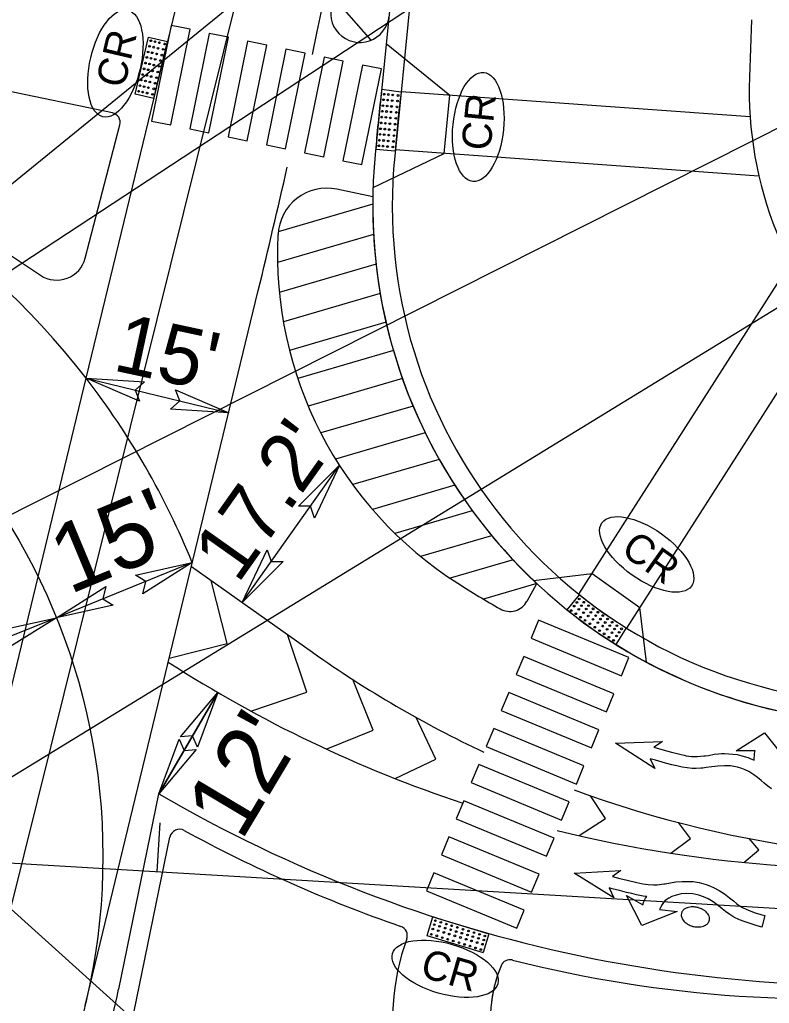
# Model space of a CAD drawing. Extents: x 2010838 to 2015151, y 441905 to 447792.
# Drawn here: x 2012023.9 to 2012100.7, y 444972.1 to 445072.8 of the extents above; entities that cross this region are included whole.
import ezdxf

# ---------------------------------------------------------------- set-up
doc = ezdxf.new("R2010")
doc.units = 0
for name, color, linetype in [('1-BUFFER', 7, 'Continuous'), ('A-Wall-Abov', 7, 'Continuous'), ('C-Alignment Geometry', 7, 'Continuous'), ('C-Building', 7, 'Continuous'), ('C-CURB STOPS', 7, 'Continuous'), ('C-Grave Plots', 7, 'Continuous'), ('C-Surface', 7, 'Continuous'), ('CLRD', 7, 'Continuous'), ('Default_10ft_LIDAR_Contou', 7, 'Continuous'), ('HATCH', 7, 'Continuous'), ('s-Existing Major', 7, 'Continuous'), ('S-Existing Minor', 7, 'Continuous'), ('S-overhead electric', 7, 'Continuous'), ('TEXT-LG', 7, 'Continuous'), ('TEXT-MED', 7, 'Continuous'), ('X4', 7, 'Continuous')]:
    doc.layers.add(name, color=color, linetype=linetype)

msp = doc.modelspace()

# ---------------------------------------------------------------- linework, layer by layer
at = {"layer": '1-BUFFER'}
msp.add_line((2012098.84, 445072.81), (2012098.63, 445066.91), dxfattribs=at)
msp.add_arc((2012137.61, 445065.53), 39, 177.9766, 273.0671, dxfattribs=at)
at = {"layer": 'A-Wall-Abov'}
msp.add_lwpolyline([(2012100.89, 444994.06), (2012100.5, 444994.33), (2012100.14, 444994.62), (2012099.83, 444994.91), (2012099.45, 444995.21), (2012099.08, 444995.49), (2012098.57, 444995.81), (2012098.2, 444996), (2012097.84, 444996.14), (2012097.42, 444996.26), (2012097.05, 444996.34), (2012096.71, 444996.39), (2012096.46, 444996.4), (2012096.09, 444996.39), (2012095.4, 444996.35), (2012094.77, 444996.29), (2012094.2, 444996.22), (2012093.85, 444996.17), (2012093.67, 444996.15), (2012093.19, 444996.12), (2012092.76, 444996.13), (2012092.26, 444996.18), (2012091.74, 444996.27), (2012091.19, 444996.39), (2012090.7, 444996.51), (2012090.05, 444996.69), (2012089.03, 444996.98), (2012088.48, 444997.13), (2012088.94, 444996.12), (2012084.93, 444998.73), (2012089.72, 444998.88), (2012088.89, 444998.32), (2012088.85, 444998.3), (2012090.13, 444997.94), (2012090.78, 444997.77), (2012091.09, 444997.69), (2012091.63, 444997.56), (2012091.94, 444997.48), (2012092.14, 444997.44), (2012092.69, 444997.37), (2012093.06, 444997.36), (2012093.33, 444997.36), (2012093.62, 444997.38), (2012093.95, 444997.41), (2012094.15, 444997.43), (2012094.45, 444997.47), (2012095.03, 444997.58), (2012095.45, 444997.63), (2012095.77, 444997.65), (2012096.07, 444997.65), (2012096.52, 444997.64), (2012096.92, 444997.61), (2012097.39, 444997.55), (2012097.86, 444997.44), (2012098.24, 444997.33), (2012098.51, 444997.24), (2012098.71, 444997.16), (2012099.1, 444996.98), (2012099.11, 444997.18), (2012099.14, 444997.47), (2012099.16, 444997.66), (2012099.21, 444997.94), (2012097.29, 444997.93), (2012100.18, 444999.79), (2012102.59, 444996.74)], dxfattribs=at)
msp.add_lwpolyline([(2012080.69, 444985.42), (2012085.48, 444985.67), (2012084.63, 444985.07), (2012085.38, 444984.88), (2012086.11, 444984.69), (2012087.12, 444984.45), (2012087.72, 444984.32), (2012088.27, 444984.24), (2012088.81, 444984.22), (2012089.2, 444984.23), (2012089.88, 444984.31), (2012090.02, 444984.32), (2012091.11, 444984.52), (2012091.74, 444984.57), (2012092.33, 444984.57), (2012092.86, 444984.54), (2012093.5, 444984.44), (2012094.19, 444984.25), (2012094.66, 444984.07), (2012094.96, 444983.94), (2012095.52, 444983.63), (2012096.07, 444983.28), (2012096.6, 444982.9), (2012096.99, 444982.59), (2012097.32, 444982.31), (2012097.52, 444982.13), (2012097.91, 444981.9), (2012098.6, 444981.57), (2012099.22, 444981.33), (2012099.79, 444981.16), (2012100.22, 444981.06), (2012099.91, 444979.87), (2012099.31, 444980.04), (2012098.69, 444980.24), (2012098.08, 444980.45), (2012097.61, 444980.63), (2012097.03, 444980.92), (2012096.61, 444981.17), (2012096.18, 444981.47), (2012095.84, 444981.76), (2012095.47, 444982.07), (2012094.91, 444982.47), (2012094.41, 444982.77), (2012093.93, 444983), (2012093.45, 444983.16), (2012092.83, 444983.29), (2012092.24, 444983.33), (2012091.64, 444983.3), (2012091.13, 444983.17), (2012090.69, 444983.02), (2012090.37, 444982.86), (2012090.02, 444982.62), (2012089.83, 444982.41), (2012089.69, 444982.21), (2012089.52, 444981.89), (2012089.44, 444981.69), (2012091.25, 444981.5), (2012087.63, 444980.06), (2012086.06, 444983.12), (2012087.71, 444982.15), (2012087.8, 444982.42), (2012087.89, 444982.63), (2012088, 444982.84), (2012088.13, 444983.02), (2012087.75, 444983.07), (2012087.09, 444983.19), (2012086.58, 444983.31), (2012086.06, 444983.44), (2012085.35, 444983.62), (2012084.6, 444983.81), (2012084.27, 444983.9), (2012084.76, 444982.9)], close=True, dxfattribs=at)
for centre, radius, start, end in [((2012092.39, 444981.11), 0.742, 166.791, 189.9046), ((2012092.27, 444981.14), 0.613, 165.5576, 166.791), ((2012092.39, 444981.11), 0.742, 141.2106, 164.3242), ((2012092.27, 444981.14), 0.613, 164.3242, 165.5576), ((2012092.42, 444981.09), 0.777, 121.0097, 141.2106), ((2012092.74, 444980.55), 1.4, 98.2802, 121.0097), ((2012092.83, 444979.95), 2.01, 90.2953, 98.2802), ((2012092.83, 444979.85), 2.1, 77.5962, 90.2953), ((2012092.86, 444979.97), 1.98, 75.5576, 77.5962), ((2012092.86, 444979.97), 1.98, 73.5191, 75.5576), ((2012092.82, 444979.86), 2.1, 60.8199, 73.5191), ((2012092.87, 444979.94), 2.01, 52.835, 60.8199), ((2012093.24, 444980.43), 1.4, 30.1056, 52.835), ((2012092.43, 444981.12), 0.777, 189.9046, 210.1056), ((2012092.97, 444981.43), 1.4, 210.1056, 232.835), ((2012093.34, 444981.92), 2.01, 232.835, 240.8199), ((2012093.78, 444980.77), 0.777, 301.0097, 321.2106), ((2012093.81, 444980.75), 0.742, 321.2106, 344.3242), ((2012093.77, 444980.74), 0.777, 9.9046, 30.1056), ((2012093.93, 444980.71), 0.613, 344.3242, 345.5576), ((2012093.81, 444980.74), 0.742, 346.791, 9.9046), ((2012093.93, 444980.71), 0.613, 345.5576, 346.791), ((2012093.38, 444982), 2.1, 240.8199, 253.5191), ((2012093.35, 444981.88), 1.98, 253.5191, 255.5576), ((2012093.35, 444981.88), 1.98, 255.5576, 257.5962), ((2012093.37, 444982), 2.1, 257.5962, 270.2953), ((2012093.37, 444981.91), 2.01, 270.2953, 278.2802), ((2012093.46, 444981.3), 1.4, 278.2802, 301.0097)]:
    msp.add_arc(centre, radius, start, end, dxfattribs=at)
at = {"layer": 'C-Alignment Geometry'}
for p, q in [((2012059.93, 445070.71), (2012056.15, 445075.02)), ((2012060.09, 445054.68), (2012056.39, 445055.45)), ((2012060.08, 445053.92), (2012050.4, 445051.09)), ((2012060.16, 445050.82), (2012050.34, 445047.95)), ((2012060.42, 445047.77), (2012050.52, 445044.88)), ((2012060.85, 445044.77), (2012050.93, 445041.87)), ((2012061.44, 445041.82), (2012051.57, 445038.93)), ((2012062.2, 445038.92), (2012052.41, 445036.06)), ((2012063.12, 445036.06), (2012053.48, 445033.24)), ((2012064.21, 445033.25), (2012054.76, 445030.49)), ((2012065.46, 445030.49), (2012056.28, 445027.81)), ((2012066.89, 445027.78), (2012058.03, 445025.2)), ((2012068.48, 445025.13), (2012060.05, 445022.66)), ((2012070.27, 445022.52), (2012062.35, 445020.21)), ((2012072.25, 445019.97), (2012064.98, 445017.85)), ((2012074.44, 445017.49), (2012068, 445015.61)), ((2012041.52, 445016.81), (2012053.92, 445008.03)), ((2012045.19, 445008.94), (2012043.53, 445015.39)), ((2012076.86, 445015.07), (2012071.4, 445013.48)), ((2012075.87, 445013.25), (2012076.86, 445015.07)), ((2012053.35, 445003.94), (2012051.37, 445009.84)), ((2012039.24, 445007.41), (2012045.19, 445008.94)), ((2012060.14, 445000.07), (2012058.04, 445005.24)), ((2012047.6, 445002), (2012053.35, 445003.94)), ((2012066.54, 444997.08), (2012064.52, 445001.36)), ((2012055.32, 444998.12), (2012060.14, 445000.07)), ((2012062.36, 444995.1), (2012066.54, 444997.08)), ((2012083.89, 444991), (2012082.36, 444993.34)), ((2012081.21, 444989.25), (2012083.89, 444991)), ((2012092.6, 444988.97), (2012091.37, 444990.6)), ((2012090.59, 444987.45), (2012092.6, 444988.97)), ((2012099.59, 444987.8), (2012098.61, 444988.96)), ((2012098.06, 444986.51), (2012099.59, 444987.8))]:
    msp.add_line(p, q, dxfattribs=at)
for centre, radius, start, end in [((2012058.77, 445073.48), 3, 158.7576, 354.3112), ((2012055.38, 445050.55), 5, 78.3258, 177.1205), ((2012113.08, 445053.77), 53, 179.0086, 226.8952), ((2012090.33, 445048.79), 40, 177.1205, 237.3974), ((2012123.2, 445100.18), 101, 237.3974, 240.2776), ((2012074.11, 445014.21), 2, 240.2776, 331.4352), ((2012120.39, 445101.87), 115, 234.6891, 244.8198), ((2012110.81, 445117.89), 132, 237.1243, 251.6722), ((2012120.39, 445101.87), 115, 249.8036, 276.5188), ((2012110.81, 445117.89), 132, 256.0409, 276.5188)]:
    msp.add_arc(centre, radius, start, end, dxfattribs=at)
at = {"layer": 'C-Building'}
msp.add_line((2012038.03, 444985.56), (2012038.32, 444990.55), dxfattribs=at)
msp.add_line((2012038.03, 444985.56), (2012038.32, 444990.55), dxfattribs=at)
at = {"layer": 'C-CURB STOPS'}
for p, q in [((2012033.44, 445063.27), (2012021.92, 445065.66)), ((2012033.44, 445063.27), (2012021.92, 445065.66)), ((2012030.65, 445048.38), (2012034.2, 445062.04)), ((2012012.92, 445055.41), (2012026.09, 445046.64)), ((2012033.57, 444961.05), (2012039.32, 444989.1))]:
    msp.add_line(p, q, dxfattribs=at)
for centre, radius, start, end in [((2012033.23, 445062.29), 1, 345.4369, 78.2618), ((2012033.23, 445062.29), 1, 345.4369, 78.2618), ((2012027.75, 445049.14), 3, 236.3341, 345.4369), ((2012108.5, 445047.19), 45, 231.2422, 238.9976), ((2012113.08, 445053.77), 53, 238.4116, 263.6479), ((2012040.3, 444988.9), 1, 61.337, 168.4243), ((2012110.81, 445117.89), 146, 241.337, 250.8656), ((2012062.62, 444979.01), 1, 340.3361, 70.8656), ((2012087.1, 444970.26), 25, 160.3361, 191.8302), ((2012074.14, 444975.55), 1, 75.7796, 157.829), ((2012106.32, 445102.53), 130, 255.7796, 276.5188), ((2012087.1, 444970.26), 15, 157.4769, 191.8302), ((2012087.1, 444970.26), 15, 157.829, 191.8302)]:
    msp.add_arc(centre, radius, start, end, dxfattribs=at)
at = {"layer": 'C-Surface'}
msp.add_line((2012016.06, 444975.4), (2012030.76, 445036.09), dxfattribs=at)
at = {"layer": 'CLRD'}
msp.add_line((2011239.41, 445032.63), (2013147.4, 444920.16), dxfattribs=at)
msp.add_arc((2011767.49, 445206.16), 285, 319.8445, 356.5533, dxfattribs=at)
at = {"layer": 'Default_10ft_LIDAR_Contou'}
for p, q in [((2012172.29, 445177.43), (2011992.07, 445030.69)), ((2011985.31, 445022.37), (2012164.65, 445140.22)), ((2012163.63, 445093), (2011959.68, 444990.17)), ((2012017.26, 444991.69), (2012152.04, 445074.34)), ((2012125.28, 444889.75), (2012017.46, 444986.77))]:
    msp.add_line(p, q, dxfattribs=at)
at = {"layer": 'HATCH'}
for p, q in [((2012039.44, 445072.23), (2012037.44, 445062.43)), ((2012041.4, 445071.83), (2012039.44, 445072.23)), ((2012039.4, 445062.03), (2012041.4, 445071.83)), ((2012043.35, 445071.41), (2012041.36, 445061.62)), ((2012043.32, 445061.22), (2012045.31, 445071.02)), ((2012045.31, 445071.02), (2012043.35, 445071.41)), ((2012047.27, 445070.6), (2012045.27, 445060.8)), ((2012047.23, 445060.41), (2012049.23, 445070.2)), ((2012049.23, 445070.2), (2012047.27, 445070.6)), ((2012051.19, 445069.79), (2012049.19, 445059.99)), ((2012051.15, 445059.59), (2012053.15, 445069.39)), ((2012053.15, 445069.39), (2012051.19, 445069.79)), ((2012055.1, 445068.98), (2012053.11, 445059.18)), ((2012057.06, 445068.58), (2012055.1, 445068.98)), ((2012055.07, 445058.78), (2012057.06, 445068.58)), ((2012059.02, 445068.17), (2012057.02, 445058.37)), ((2012060.98, 445067.77), (2012059.02, 445068.17)), ((2012058.98, 445057.97), (2012060.98, 445067.77)), ((2012037.44, 445062.43), (2012039.4, 445062.03)), ((2012041.36, 445061.62), (2012043.32, 445061.22)), ((2012045.27, 445060.8), (2012047.23, 445060.41)), ((2012049.19, 445059.99), (2012051.15, 445059.59)), ((2012053.11, 445059.18), (2012055.07, 445058.78)), ((2012057.02, 445058.37), (2012058.98, 445057.97)), ((2012030.64, 444971.87), (2012048.37, 445045.09)), ((2012046.72, 445013.13), (2012056.67, 445027.19)), ((2012077.06, 445011.31), (2012076.29, 445009.46)), ((2012086.3, 445007.48), (2012077.06, 445011.31)), ((2012076.29, 445009.46), (2012085.53, 445005.63)), ((2012075.53, 445007.61), (2012074.76, 445005.76)), ((2012084.77, 445003.78), (2012075.53, 445007.61)), ((2012085.53, 445005.63), (2012086.3, 445007.48)), ((2012074.76, 445005.76), (2012084, 445001.93)), ((2012038.18, 444993.54), (2012044.24, 445003.91)), ((2012074, 445003.92), (2012073.23, 445002.07)), ((2012083.23, 445000.09), (2012074, 445003.92)), ((2012084, 445001.93), (2012084.77, 445003.78)), ((2012073.23, 445002.07), (2012082.47, 444998.24)), ((2012072.46, 445000.22), (2012071.7, 444998.37)), ((2012081.7, 444996.39), (2012072.46, 445000.22)), ((2012082.47, 444998.24), (2012083.23, 445000.09)), ((2012071.7, 444998.37), (2012080.93, 444994.54)), ((2012070.93, 444996.53), (2012070.17, 444994.68)), ((2012080.17, 444992.7), (2012070.93, 444996.53)), ((2012080.93, 444994.54), (2012081.7, 444996.39)), ((2012070.17, 444994.68), (2012079.4, 444990.85)), ((2012069.4, 444992.83), (2012068.63, 444990.98)), ((2012078.64, 444989), (2012069.4, 444992.83)), ((2012079.4, 444990.85), (2012080.17, 444992.7)), ((2012068.63, 444990.98), (2012077.87, 444987.15)), ((2012067.87, 444989.14), (2012067.1, 444987.29)), ((2012077.1, 444985.31), (2012067.87, 444989.14)), ((2012077.87, 444987.15), (2012078.64, 444989)), ((2012067.1, 444987.29), (2012076.34, 444983.46)), ((2012066.33, 444985.44), (2012065.57, 444983.59)), ((2012075.57, 444981.61), (2012066.33, 444985.44)), ((2012076.34, 444983.46), (2012077.1, 444985.31)), ((2012065.57, 444983.59), (2012074.81, 444979.76)), ((2012074.81, 444979.76), (2012075.57, 444981.61))]:
    msp.add_line(p, q, dxfattribs=at)
msp.add_circle((2011967.46, 444987.16), 65, dxfattribs=at)
for centre, radius, start, end in [((2011076.45, 445280.41), 1000, 347.80893, 356.71393), ((2011076.45, 445280.41), 1000, 346.38954, 347.13177), ((2011967.46, 444987.16), 80, 22.0486, 37.7074)]:
    msp.add_arc(centre, radius, start, end, dxfattribs=at)
at = {"layer": 's-Existing Major'}
for points in [[(2012036.2, 445033.74), (2012030.76, 445036.09), (2012036.72, 445035.72), (2012035.75, 445034.88)], [(2012039.89, 445034.92), (2012045.34, 445032.56), (2012039.37, 445032.94), (2012040.34, 445033.77)], [(2012052.47, 445022.99), (2012056.67, 445027.19), (2012054.12, 445021.78), (2012053.7, 445023)], [(2012050.92, 445017.32), (2012046.72, 445013.13), (2012049.27, 445018.53), (2012049.68, 445017.32)], [(2012035.81, 445015.94), (2012041.61, 445017.21), (2012036.55, 445014.03), (2012036.85, 445015.28)], [(2012033.51, 445012.84), (2012027.71, 445011.57), (2012032.77, 445014.75), (2012032.47, 445013.5)], [(2012021.91, 445010.31), (2012027.71, 445011.57), (2012022.65, 445008.4), (2012022.95, 445009.65)], [(2012040.41, 444999.36), (2012044.24, 445003.9), (2012042.16, 444998.3), (2012041.64, 444999.47)], [(2012042.01, 444998.08), (2012038.18, 444993.54), (2012040.26, 444999.14), (2012040.78, 444997.97)]]:
    msp.add_lwpolyline(points, close=True, dxfattribs=at)
at = {"layer": 'S-Existing Minor'}
for p, q in [((2011915.11, 444547.35), (2012067.43, 445160.54)), ((2012030.76, 445036.09), (2012045.34, 445032.56)), ((2012046.72, 445013.13), (2012056.67, 445027.19)), ((2012041.61, 445017.21), (2012027.71, 445011.57)), ((2012027.71, 445011.57), (2012013.8, 445005.94)), ((2012044.24, 445003.9), (2012038.18, 444993.54))]:
    msp.add_line(p, q, dxfattribs=at)
at = {"layer": 'S-overhead electric'}
for p, q in [((2012030.76, 445036.09), (2012041.66, 445081.14)), ((2012062.37, 445079.41), (2012060.34, 445059.02)), ((2012034.08, 444973.52), (2012038.18, 444993.54))]:
    msp.add_line(p, q, dxfattribs=at)
for centre, radius, start, end in [((2011967.46, 444987.16), 80, 37.7074, 77.8866), ((2012113.08, 445053.77), 53, 174.3112, 263.6479), ((2012110.81, 445117.89), 144, 239.714, 276.5188), ((2011967.46, 444987.16), 68, 328.4998, 348.4243), ((2012194.53, 444272.36), 700, 86.62643, 103.97797)]:
    msp.add_arc(centre, radius, start, end, dxfattribs=at)
at = {"layer": 'TEXT-LG'}
for p, q in [((2012035.75, 445065.2), (2012037.14, 445071.03)), ((2012037.14, 445071.03), (2012039.09, 445070.57)), ((2012037.69, 445064.73), (2012039.09, 445070.57)), ((2012061.47, 445070.36), (2012067.98, 445065.08)), ((2012037.69, 445064.73), (2012035.75, 445065.2)), ((2012061.01, 445065.7), (2012062.99, 445065.44)), ((2012098.7, 445062.86), (2012062.99, 445065.44)), ((2012067.38, 445059.11), (2012067.98, 445065.08)), ((2012060.11, 445055.63), (2012067.38, 445059.11)), ((2012062.38, 445059.36), (2012060.39, 445059.51)), ((2012099.6, 445056.78), (2012062.39, 445059.47)), ((2012081.17, 445013.98), (2012102.84, 445047.87)), ((2012086.07, 445010.5), (2012106.34, 445042.22)), ((2012076.54, 445015.37), (2012082.53, 445016.1)), ((2012082.53, 445016.1), (2012087.43, 445012.62)), ((2012079.99, 445012.36), (2012081.25, 445013.91)), ((2012088.09, 445007.03), (2012087.43, 445012.62)), ((2012086.01, 445010.54), (2012084.97, 445008.84)), ((2012065.64, 444979.02), (2012066.22, 444980.93)), ((2012066.22, 444980.93), (2012071.96, 444979.18)), ((2012071.96, 444979.18), (2012071.37, 444977.27)), ((2012065.63, 444979.02), (2012071.37, 444977.27))]:
    msp.add_line(p, q, dxfattribs=at)
for centre in [(2012037.24, 445070.09), (2012037.37, 445070.65), (2012037.66, 445070), (2012037.79, 445070.56), (2012038.1, 445069.89), (2012038.24, 445070.45), (2012038.64, 445069.77), (2012038.78, 445070.32), (2012036.96, 445068.95), (2012037.09, 445069.51), (2012037.38, 445068.86), (2012037.51, 445069.42), (2012037.82, 445068.75), (2012037.96, 445069.31), (2012038.5, 445069.18), (2012036.68, 445067.78), (2012036.82, 445068.37), (2012037.24, 445068.28), (2012037.68, 445068.16), (2012038.22, 445068.04), (2012038.36, 445068.63), (2012036.54, 445067.19), (2012036.96, 445067.1), (2012037.1, 445067.68), (2012037.4, 445066.99), (2012037.54, 445067.57), (2012037.94, 445066.87), (2012038.08, 445067.45), (2012036.26, 445066.05), (2012036.4, 445066.63), (2012036.68, 445065.96), (2012036.82, 445066.54), (2012037.12, 445065.85), (2012037.27, 445066.43), (2012037.67, 445065.73), (2012037.81, 445066.31), (2012036.12, 445065.49), (2012036.54, 445065.4), (2012036.99, 445065.29), (2012037.53, 445065.17), (2012061.24, 445065.18), (2012061.67, 445065.15), (2012062.12, 445065.1), (2012062.68, 445065.05), (2012061.12, 445064.01), (2012061.18, 445064.61), (2012061.55, 445063.98), (2012061.61, 445064.58), (2012062, 445063.93), (2012062.07, 445064.52), (2012062.56, 445063.88), (2012062.62, 445064.48), (2012061, 445062.84), (2012061.06, 445063.44), (2012061.43, 445062.81), (2012061.49, 445063.41), (2012061.88, 445062.76), (2012061.95, 445063.36), (2012062.44, 445062.71), (2012062.5, 445063.31), (2012060.94, 445062.24), (2012061.37, 445062.2), (2012061.83, 445062.15), (2012062.38, 445062.11), (2012060.82, 445061.07), (2012060.88, 445061.64), (2012061.25, 445061.04), (2012061.31, 445061.61), (2012061.71, 445060.99), (2012061.77, 445061.56), (2012062.26, 445060.94), (2012062.32, 445061.51), (2012060.7, 445059.9), (2012060.76, 445060.47), (2012061.13, 445059.87), (2012061.19, 445060.44), (2012061.59, 445059.82), (2012061.65, 445060.39), (2012062.14, 445059.77), (2012062.2, 445060.34), (2012081.21, 445013.49), (2012080.7, 445012.76), (2012080.97, 445013.13), (2012081.17, 445012.43), (2012081.44, 445012.8), (2012081.68, 445013.16), (2012081.93, 445012.46), (2012082.17, 445012.81), (2012082.63, 445012.48), (2012080.39, 445012.3), (2012080.86, 445011.97), (2012081.35, 445011.62), (2012081.66, 445012.08), (2012082.13, 445011.75), (2012082.4, 445012.12), (2012082.62, 445011.4), (2012082.89, 445011.78), (2012083.12, 445012.13), (2012083.38, 445011.43), (2012083.62, 445011.79), (2012084.11, 445011.44), (2012081.81, 445011.29), (2012082.3, 445010.95), (2012082.8, 445010.6), (2012083.12, 445011.06), (2012083.61, 445010.71), (2012083.87, 445011.08), (2012084.07, 445010.38), (2012084.34, 445010.75), (2012084.58, 445011.11), (2012084.83, 445010.41), (2012085.07, 445010.76), (2012085.54, 445010.43), (2012083.29, 445010.25), (2012083.76, 445009.92), (2012084.25, 445009.57), (2012084.56, 445010.03), (2012085.03, 445009.7), (2012085.3, 445010.07), (2012084.72, 445009.24), (2012066.38, 444980.13), (2012066.49, 444980.54), (2012067.04, 444980.37), (2012067.61, 444980.19), (2012066.08, 444979.15), (2012066.24, 444979.69), (2012066.78, 444979.52), (2012066.92, 444979.96), (2012067.36, 444979.34), (2012067.5, 444979.78), (2012067.91, 444979.17), (2012068.05, 444979.61), (2012068.16, 444980.02), (2012068.62, 444979.43), (2012068.74, 444979.85), (2012069.2, 444979.26), (2012069.32, 444979.67), (2012069.89, 444979.49), (2012070.44, 444979.32), (2012071.01, 444979.15), (2012066.63, 444978.99), (2012067.2, 444978.81), (2012067.75, 444978.64), (2012068.32, 444978.46), (2012068.48, 444978.99), (2012068.91, 444978.29), (2012069.06, 444978.82), (2012069.48, 444978.11), (2012069.64, 444978.64), (2012069.78, 444979.08), (2012070.18, 444978.47), (2012070.32, 444978.91), (2012070.76, 444978.3), (2012070.9, 444978.73), (2012071.31, 444978.13), (2012071.45, 444978.56), (2012071.56, 444978.98), (2012070.03, 444977.94), (2012070.6, 444977.76), (2012071.15, 444977.59)]:
    msp.add_circle(centre, 0.0869, dxfattribs=at)
for centre, radius, start, end in [((2012175.09, 445051.21), 115, 172.7635, 175.8623), ((2012175.09, 445051.21), 113, 172.7635, 175.8623), ((2012108.42, 445047.24), 43, 230.8107, 238.5928), ((2012108.42, 445047.24), 45, 230.8107, 238.5928)]:
    msp.add_arc(centre, radius, start, end, dxfattribs=at)
at = {"layer": 'TEXT-MED'}
msp.add_line((2012064.36, 445079.21), (2012062.33, 445058.82), dxfattribs=at)
msp.add_arc((2012113.08, 445053.77), 51, 174.3112, 263.6479, dxfattribs=at)
at = {"layer": 'X4'}
for centre, major_axis in [((2012033.74, 445068.33), (1.28, 5.46)), ((2012070.88, 445061.83), (0.56, 5.58)), ((2012088.12, 445018.05), (4.58, -3.24)), ((2012067.49, 444975.62), (5.39, -1.55))]:
    msp.add_ellipse(centre, major_axis=major_axis, ratio=0.462467, dxfattribs=at)

# ---------------------------------------------------------------- texts
at = {"layer": 'C-Grave Plots'}
for s, height, rotation, p in [("15'", 6, 347.8334, (2012033.35, 445036.93)), ("17.2'", 6, 54.6891, (2012046.27, 445014.95)), ("15'", 7, 22.5868, (2012029.03, 445013.92)), ("12'", 7, 59.1699, (2012046.62, 444988.59))]:
    msp.add_text(s, height=height, rotation=rotation, dxfattribs=at).set_placement(p)
at = {"layer": 'X4'}
for rotation, p in [(76.8504, (2012034.64, 445065.7)), (84.3112, (2012072.12, 445059.33)), (324.6875, (2012085.34, 445018.2)), (343.9274, (2012064.81, 444974.85))]:
    msp.add_text('CR', height=3, rotation=rotation, dxfattribs=at).set_placement(p)

doc.saveas('drawing.dxf')
